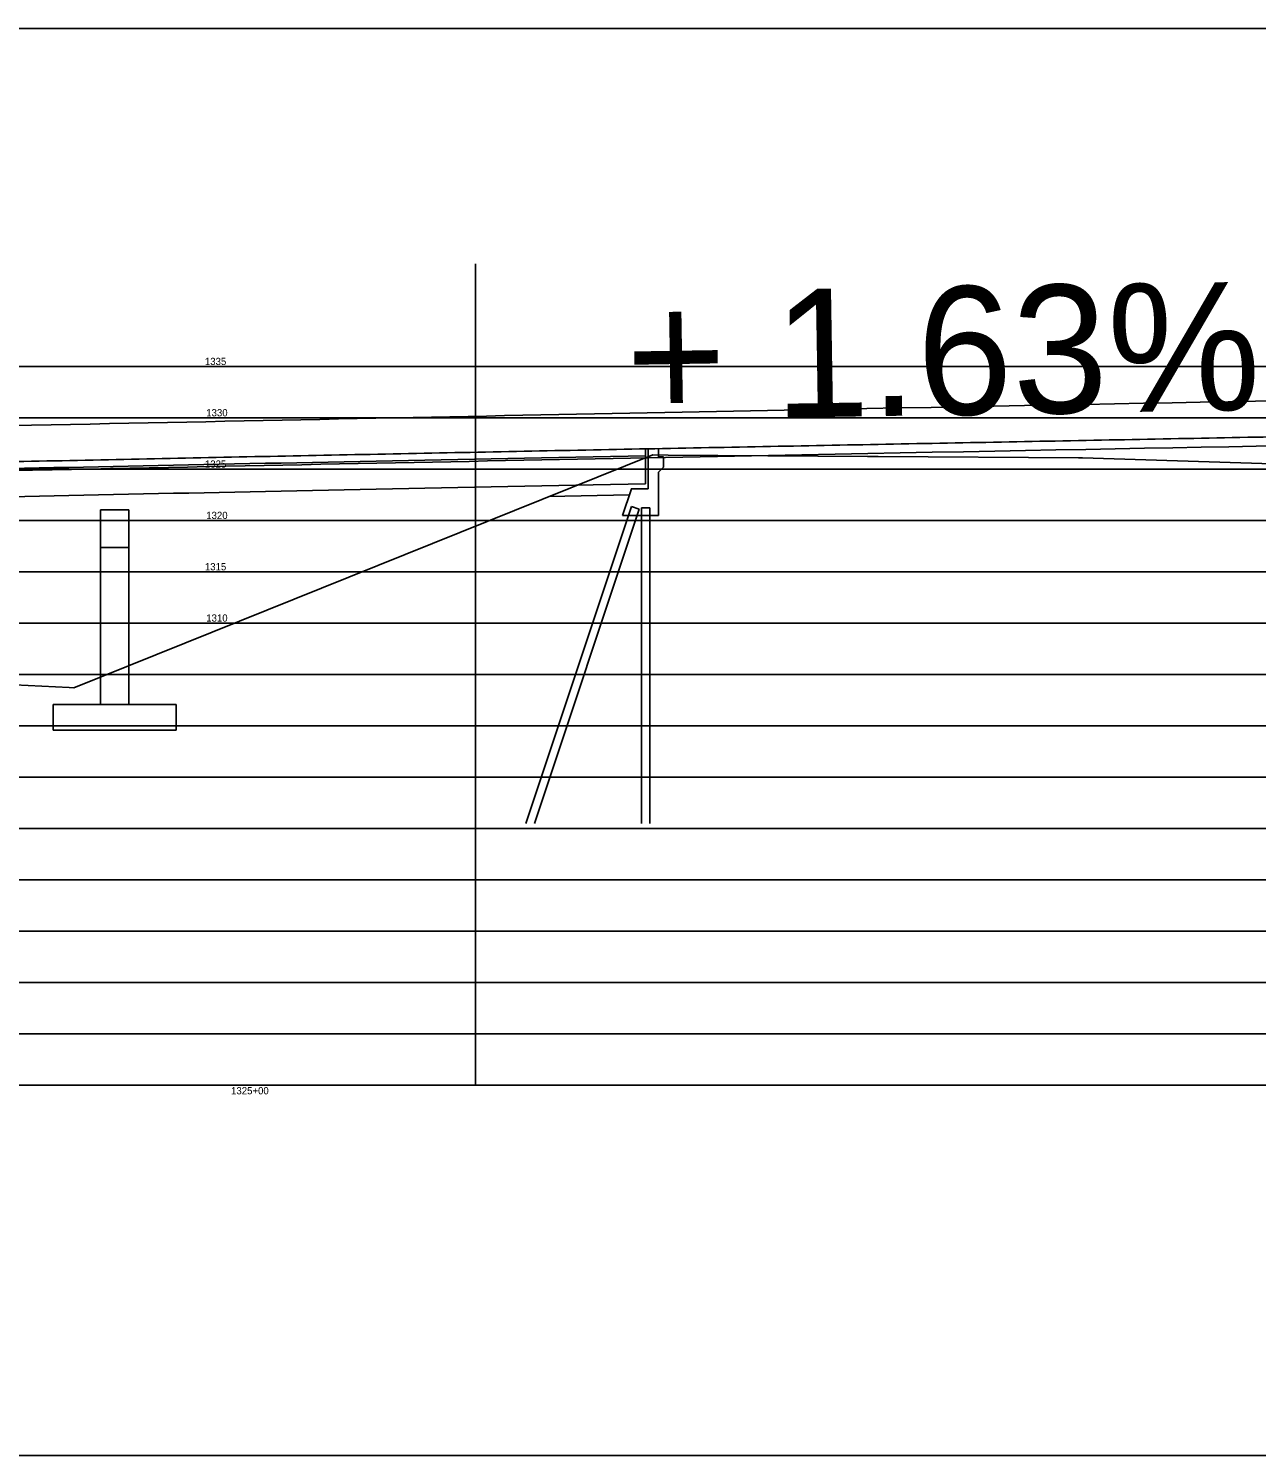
# Model space of a CAD drawing. Extents: x 680639 to 702326, y 743523 to 756592.
# Drawn here: x 688682.2 to 688801.8, y 751717.1 to 751856.1 of the extents above; entities that cross this region are included whole.
import ezdxf

# ---------------------------------------------------------------- set-up
doc = ezdxf.new("R2010")
doc.units = 0
for name, color, linetype in [('B_Concrete', 7, 'Continuous'), ('B_Existing Structure', 7, 'Continuous'), ('B_Proposed Ground', 7, 'Continuous'), ('B_Steel', 7, 'Continuous'), ('Default', 7, 'Continuous'), ('R_Axis', 7, 'Continuous'), ('R_Axis Annot', 7, 'Continuous'), ('R_Exist Surface', 7, 'Continuous'), ('R_No Plot', 7, 'Continuous'), ('R_Vert Alg', 7, 'Continuous')]:
    doc.layers.add(name, color=color, linetype=linetype)

msp = doc.modelspace()

# ---------------------------------------------------------------- linework, layer by layer
at = {"layer": 'B_Concrete'}
for p, q in [((688742.57, 751811.27), (688742.57, 751815.17)), ((688743.57, 751814.4), (688743.57, 751815.19)), ((688744.07, 751814.4), (688743.57, 751814.4)), ((688744.07, 751813.4), (688744.07, 751814.4)), ((688743.57, 751812.9), (688744.07, 751813.4)), ((688743.57, 751812.9), (688743.57, 751808.68)), ((688740.07, 751808.68), (688740.9, 751811.18)), ((688740.9, 751811.18), (688740.9, 751811.27)), ((688742.57, 751811.27), (688740.9, 751811.27)), ((688743.57, 751808.68), (688740.07, 751808.68))]:
    msp.add_line(p, q, dxfattribs=at)
msp.add_open_spline([(688372.96, 751810.2), (688384.35, 751810.5), (688420.74, 751811.44), (688507.13, 751813.6), (688632.13, 751816.46), (688757.14, 751819), (688844.65, 751820.6), (688882.16, 751821.24), (688897.6, 751821.51), (688900.54, 751821.56), (688903.48, 751821.61)], degree=3, dxfattribs=at)
at = {"layer": 'B_Existing Structure'}
for p, q in [((688689.21, 751809.24), (688689.21, 751790.26)), ((688689.21, 751809.24), (688691.96, 751809.24)), ((688691.96, 751809.24), (688691.96, 751790.26)), ((688689.21, 751805.57), (688691.96, 751805.57)), ((688684.59, 751790.26), (688696.59, 751790.26)), ((688684.59, 751790.26), (688684.59, 751787.76)), ((688696.59, 751790.26), (688696.59, 751787.76)), ((688684.59, 751787.76), (688696.59, 751787.76))]:
    msp.add_line(p, q, dxfattribs=at)
at = {"layer": 'B_Proposed Ground'}
msp.add_line((688740.74, 751810.68), (688732.88, 751810.52), dxfattribs=at)
msp.add_open_spline([(688372.96, 751805.82), (688384.39, 751806.12), (688420.81, 751807.06), (688507.23, 751809.22), (688632.23, 751812.08), (688757.23, 751814.62), (688844.73, 751816.22), (688882.24, 751816.87), (688897.65, 751817.13), (688900.57, 751817.18), (688903.48, 751817.23)], degree=3, dxfattribs=at)
at = {"layer": 'B_Steel'}
for p, q in [((688742.32, 751811.76), (688742.32, 751815.17)), ((688730.64, 751778.68), (688740.94, 751809.56)), ((688741.7, 751809.31), (688740.94, 751809.56)), ((688741.91, 751778.68), (688741.91, 751809.43)), ((688742.72, 751809.43), (688741.91, 751809.43)), ((688742.72, 751778.68), (688742.72, 751809.43)), ((688731.5, 751778.68), (688741.7, 751809.31))]:
    msp.add_line(p, q, dxfattribs=at)
for points in [[(688566.65, 751810.77), (688588.51, 751811.27), (688647.06, 751812.57), (688705.62, 751813.78), (688742.32, 751814.5)], [(688566.65, 751808.04), (688588.52, 751808.53), (688647.08, 751809.83), (688705.64, 751811.04), (688742.32, 751811.76)]]:
    msp.add_open_spline(points, degree=3, dxfattribs=at)
at = {"layer": 'R_Axis'}
for p, q in [((688725.74, 751753.19), (688725.74, 751833.19)), ((688372.96, 751823.19), (688903.48, 751823.19)), ((688372.96, 751818.19), (688903.48, 751818.19)), ((688372.96, 751813.19), (688903.48, 751813.19)), ((688372.96, 751808.19), (688903.48, 751808.19)), ((688372.96, 751803.19), (688903.48, 751803.19)), ((688372.96, 751798.19), (688903.48, 751798.19)), ((688372.96, 751793.19), (688903.48, 751793.19)), ((688372.96, 751788.19), (688903.48, 751788.19)), ((688372.96, 751783.19), (688903.48, 751783.19)), ((688372.96, 751778.19), (688903.48, 751778.19)), ((688372.96, 751773.19), (688903.48, 751773.19)), ((688372.96, 751768.19), (688903.48, 751768.19)), ((688372.96, 751763.19), (688903.48, 751763.19)), ((688372.96, 751758.19), (688903.48, 751758.19)), ((688372.96, 751753.19), (688903.48, 751753.19))]:
    msp.add_line(p, q, dxfattribs=at)
at = {"layer": 'R_Exist Surface'}
msp.add_line((688686.61, 751791.89), (688743.01, 751814.6), dxfattribs=at)
msp.add_lwpolyline([(688358.07, 751856.12), (688913.85, 751856.12), (688913.85, 751717.1), (688358.07, 751717.1)], close=True, dxfattribs=at)
for points in [[(688743.01, 751814.6), (688744.5, 751814.56), (688763.95, 751814.41), (688764.49, 751814.42), (688764.99, 751814.44), (688784.48, 751814.29), (688784.9, 751814.29), (688806.48, 751813.61)], [(688680.83, 751792.18), (688686.16, 751791.91), (688686.61, 751791.89), (688686.61, 751791.9), (688686.62, 751791.93)]]:
    msp.add_lwpolyline(points, dxfattribs=at)
at = {"layer": 'R_Vert Alg'}
msp.add_spline([(688372.96, 751806.7), (688380.23, 751806.89), (688392.23, 751807.2), (688404.23, 751807.51), (688416.23, 751807.82), (688428.23, 751808.12), (688440.23, 751808.42), (688452.23, 751808.72), (688464.23, 751809.02), (688476.23, 751809.31), (688488.23, 751809.6), (688500.23, 751809.89), (688512.23, 751810.18), (688524.23, 751810.46), (688536.23, 751810.74), (688548.23, 751811.02), (688560.23, 751811.3), (688572.23, 751811.57), (688584.23, 751811.84), (688596.23, 751812.11), (688608.23, 751812.37), (688620.23, 751812.64), (688632.23, 751812.9), (688644.23, 751813.15), (688656.23, 751813.41), (688668.23, 751813.66), (688680.23, 751813.91), (688692.23, 751814.16), (688704.23, 751814.41), (688716.23, 751814.65), (688728.23, 751814.89), (688740.23, 751815.13), (688752.23, 751815.36), (688764.23, 751815.59), (688776.23, 751815.82), (688788.23, 751816.05), (688800.23, 751816.28), (688812.23, 751816.5), (688824.23, 751816.72), (688836.23, 751816.93), (688848.23, 751817.15), (688860.23, 751817.36), (688872.23, 751817.57), (688884.23, 751817.78), (688896.23, 751817.98), (688903.48, 751818.11)], degree=3, dxfattribs=at)

# ---------------------------------------------------------------- texts
at = {"layer": 'Default'}
msp.add_text('+ 1.63%', height=12.5, rotation=0.9338, dxfattribs=at).set_placement((688740.5, 751817.96))
at = {"layer": 'R_Axis Annot'}
msp.add_text('1325+00', height=0.7, dxfattribs=at).set_placement((688701.93, 751752.29))
at = {"layer": 'R_No Plot'}
for s, p in [('1335', (688699.38, 751823.34)), ('1330', (688699.51, 751818.34)), ('1325', (688699.38, 751813.34)), ('1320', (688699.51, 751808.34)), ('1315', (688699.38, 751803.34)), ('1310', (688699.51, 751798.34))]:
    msp.add_text(s, height=0.7, dxfattribs=at).set_placement(p)

doc.saveas('drawing.dxf')
